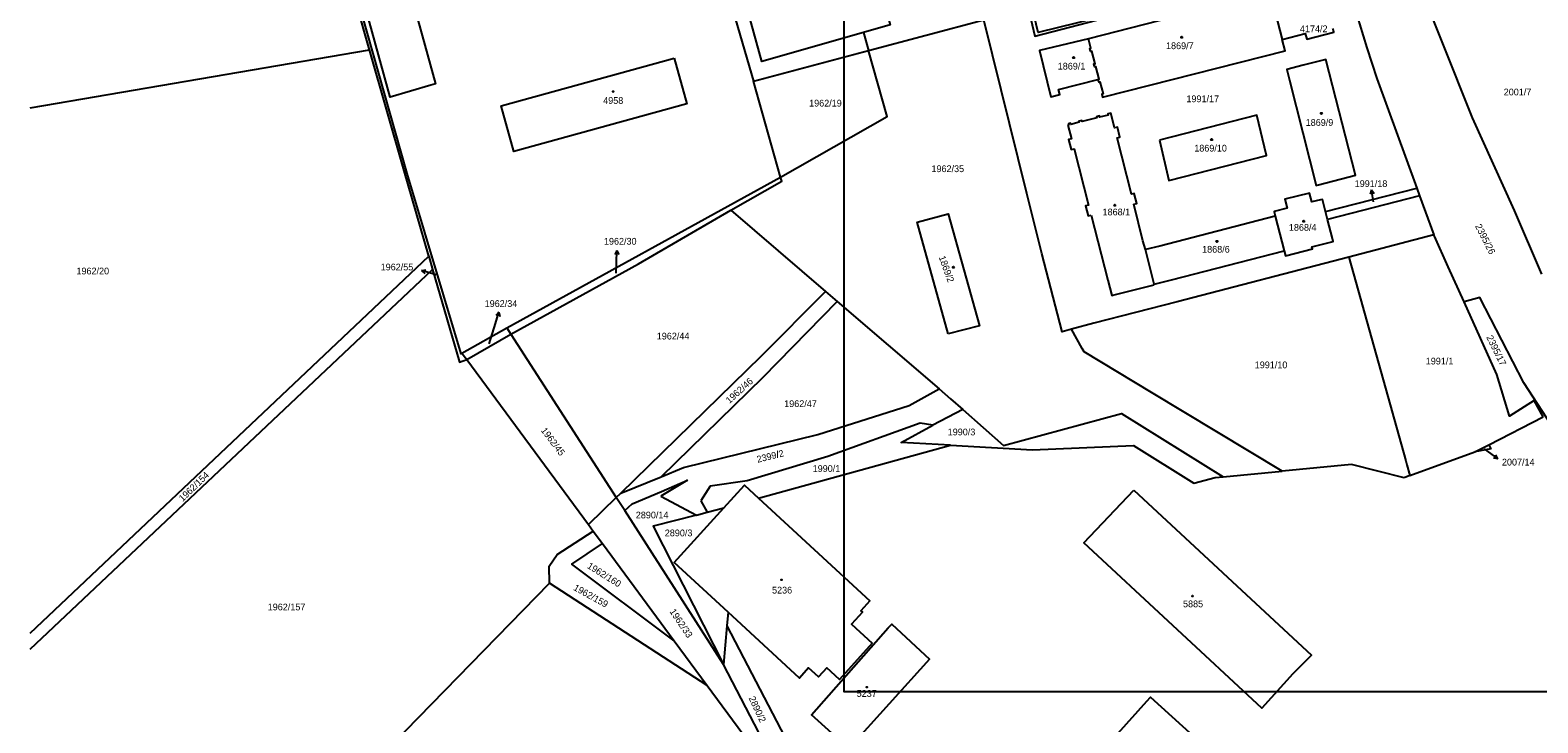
# Model space of a CAD drawing. Extents: x -667048 to -665920, y -1108425 to -1107247.
# Drawn here: x -667043.5 to -666663.6, y -1108191.2 to -1108016.8 of the extents above; entities that cross this region are included whole.
import ezdxf

# ---------------------------------------------------------------- set-up
doc = ezdxf.new("R2010")
doc.units = 0
for name, color, linetype in [('Default', 7, 'Continuous'), ('Hranice parcel', 7, 'Continuous'), ('Parcelní čísla', 7, 'Continuous'), ('Pop_ PČ_ popisy', 7, 'Continuous'), ('Vrstva 2', 7, 'Continuous'), ('Značky budov', 7, 'Continuous')]:
    doc.layers.add(name, color=color, linetype=linetype)

# ---------------------------------------------------------------- blocks, each defined once
blk = doc.blocks.new('4.021')
at = {"layer": 'Default'}
blk.add_circle((-7, 1), 175, dxfattribs=at)
blk = doc.blocks.new('10291')
at = {"layer": 'Default'}
for p, q in [((0, 3001), (-500, 2001)), ((0, 1), (0, 3001)), ((0, 3001), (500, 2001))]:
    blk.add_line(p, q, dxfattribs=at)

msp = doc.modelspace()

# ---------------------------------------------------------------- linework, layer by layer
at = {"layer": 'Hranice parcel'}
for points in [[(-666891.29, -1107926.58), (-666861.25, -1108029.69)], [(-666979.93, -1107942.01), (-666948.55, -1108052.87)], [(-666833.56, -1108017.4), (-666859.17, -1108024.68), (-666875.35, -1107965.92), (-666865.66, -1107962.99), (-666851.87, -1108012.02), (-666837.29, -1108007.83), (-666838.85, -1108002.7), (-666837.63, -1108002.35)], [(-666957.96, -1108021.81), (-666971.4, -1107974.51)], [(-666955.64, -1107978.55), (-666941.34, -1108030.34), (-666942.51, -1108030.68), (-666952.78, -1108033.65), (-666967.07, -1107981.86), (-666957.09, -1107978.97), (-666955.64, -1107978.55)], [(-666837.63, -1108002.35), (-666827.26, -1107999.36), (-666824.99, -1108006.76), (-666828.9, -1108007.97), (-666826.78, -1108015.47), (-666833.56, -1108017.4)], [(-666803.23, -1108014.21), (-666792.01, -1108011.23), (-666790.36, -1108018.29), (-666770.32, -1108013.15), (-666760.82, -1108010.71), (-666743.74, -1108006.33), (-666717.9, -1107999.7)], [(-666695.01, -1108001.76), (-666680.18, -1108038.91)], [(-666790.99, -1108011.46), (-666776.28, -1108007.84), (-666774.82, -1108013.77), (-666789.53, -1108017.38), (-666790.99, -1108011.46)], [(-666731.16, -1108007.34), (-666741.77, -1108010.04), (-666776.85, -1108018.98)], [(-666730.43, -1108010.12), (-666728.05, -1108019.21)], [(-666832.27, -1108021.94), (-666803.23, -1108014.21)], [(-666792.38, -1108057.96), (-666803.23, -1108014.21)], [(-666709.08, -1108013.58), (-666708.59, -1108015.23), (-666706.74, -1108021.23), (-666704.24, -1108029.02), (-666694.11, -1108056.64)], [(-666833.56, -1108017.4), (-666832.27, -1108021.94)], [(-666776.85, -1108018.98), (-666789.16, -1108021.98), (-666786.3, -1108033.59), (-666784.09, -1108033.03), (-666784.43, -1108031.72), (-666774.46, -1108029.2)], [(-666774.46, -1108029.2), (-666774.17, -1108029.12), (-666775, -1108025.98), (-666775.29, -1108026.06), (-666775.48, -1108025.33), (-666775.19, -1108025.26), (-666776.02, -1108022.12), (-666776.31, -1108022.2), (-666776.5, -1108021.47), (-666776.22, -1108021.39), (-666776.85, -1108018.98)], [(-666774.46, -1108029.2), (-666774.37, -1108029.56), (-666774.27, -1108029.92), (-666773.98, -1108029.85), (-666773.18, -1108032.89), (-666773.47, -1108032.97), (-666773.28, -1108033.69), (-666772.99, -1108033.61), (-666727.32, -1108021.99), (-666728.05, -1108019.21)], [(-666728.05, -1108019.21), (-666722.24, -1108017.68), (-666721.84, -1108019.07), (-666715.02, -1108017.34), (-666715.23, -1108016.53), (-666715.26, -1108016.42)], [(-667043.46, -1108036.37), (-666957.96, -1108021.81)], [(-666949.22, -1108052.27), (-666957.96, -1108021.81)], [(-666861.25, -1108029.69), (-666832.27, -1108021.94)], [(-666854.42, -1108053.87), (-666827.55, -1108038.58), (-666832.27, -1108021.94)], [(-666881.2, -1108023.83), (-666878.02, -1108035.4), (-666921.62, -1108047.4), (-666924.79, -1108035.83), (-666881.2, -1108023.83)], [(-666722.73, -1108025.66), (-666726.86, -1108026.72), (-666726.18, -1108029.4), (-666719.45, -1108055.9), (-666719.35, -1108055.88), (-666718.87, -1108055.75), (-666709.61, -1108053.31), (-666717.05, -1108024.2), (-666722.73, -1108025.66)], [(-666854.42, -1108053.87), (-666861.25, -1108029.69)], [(-666771.17, -1108037.99), (-666771.24, -1108037.69), (-666771.98, -1108037.88), (-666771.91, -1108038.18), (-666774.03, -1108038.71), (-666774.1, -1108038.41), (-666774.84, -1108038.6), (-666774.77, -1108038.9), (-666778.44, -1108039.83), (-666778.52, -1108039.53), (-666779.27, -1108039.72), (-666779.19, -1108040.02), (-666781.29, -1108040.55), (-666781.37, -1108040.25), (-666781.86, -1108040.38), (-666781.79, -1108040.67), (-666782.01, -1108040.73)], [(-666765.41, -1108060.66), (-666764.68, -1108060.48), (-666765.32, -1108057.97), (-666766.04, -1108058.15), (-666769.65, -1108043.97), (-666768.92, -1108043.79), (-666769.56, -1108041.27), (-666770.29, -1108041.45), (-666771.17, -1108037.99)], [(-666758.98, -1108044.5), (-666756.6, -1108054.63), (-666731.98, -1108048.38), (-666734.45, -1108038.18), (-666758.98, -1108044.5)], [(-666782.01, -1108040.73), (-666781.12, -1108044.19), (-666781.85, -1108044.37), (-666781.2, -1108046.89), (-666780.47, -1108046.7), (-666776.83, -1108060.84), (-666777.56, -1108061.03), (-666776.91, -1108063.55), (-666776.19, -1108063.36)], [(-666680.18, -1108038.91), (-666669.62, -1108062.22)], [(-666949.22, -1108052.27), (-666948.55, -1108052.87)], [(-666943.03, -1108073.7), (-666949.22, -1108052.27)], [(-666948.55, -1108052.87), (-666934.94, -1108098.28), (-666934.67, -1108098.13)], [(-666923.4, -1108091.78), (-666854.42, -1108053.87)], [(-666866.92, -1108062.13), (-666854.13, -1108054.85), (-666854.42, -1108053.87)], [(-666717.13, -1108062.49), (-666694.11, -1108056.64)], [(-666694.11, -1108056.64), (-666693.42, -1108058.53)], [(-666781.15, -1108092.07), (-666783.45, -1108092.77), (-666788.61, -1108073.09), (-666792.38, -1108057.96)], [(-666762.51, -1108072.05), (-666763.12, -1108069.85), (-666765.41, -1108060.66)], [(-666717.13, -1108062.49), (-666717.91, -1108059.42), (-666718.4, -1108059.54), (-666720.56, -1108060.08), (-666721.13, -1108057.82), (-666727.39, -1108059.41), (-666726.83, -1108061.64), (-666730.09, -1108062.46), (-666729.79, -1108063.67)], [(-666693.42, -1108058.53), (-666716.62, -1108064.47)], [(-666693.42, -1108058.53), (-666689.81, -1108068.36)], [(-666922.37, -1108093.38), (-666890.21, -1108075.64), (-666866.92, -1108062.13)], [(-666866.92, -1108062.13), (-666843.08, -1108082.6)], [(-666812.18, -1108093.28), (-666820.02, -1108065.2), (-666812.23, -1108063.05), (-666804.31, -1108091.26), (-666812.18, -1108093.28)], [(-666776.19, -1108063.36), (-666771.96, -1108079.76), (-666770.97, -1108083.64), (-666770.72, -1108083.58), (-666760.29, -1108080.91)], [(-666729.79, -1108063.67), (-666758.89, -1108071.24), (-666762.51, -1108072.05)], [(-666729.79, -1108063.67), (-666727.54, -1108072.39)], [(-666727.54, -1108072.39), (-666727.23, -1108073.6), (-666720.41, -1108071.86), (-666720.54, -1108071.38), (-666715.2, -1108070.01), (-666715.39, -1108069.29), (-666716.62, -1108064.47)], [(-666716.62, -1108064.47), (-666717.13, -1108062.49)], [(-666669.62, -1108062.22), (-666662.76, -1108078.25)], [(-666689.81, -1108068.36), (-666711.24, -1108074.01)], [(-666682.24, -1108085.26), (-666686.2, -1108076.44), (-666689.69, -1108068.69), (-666689.81, -1108068.36)], [(-666760.33, -1108080.77), (-666762.51, -1108072.05)], [(-666760.33, -1108080.77), (-666755.93, -1108079.65), (-666727.54, -1108072.39)], [(-667043.46, -1108168.6), (-666943.03, -1108073.7)], [(-666943.03, -1108073.7), (-666942.06, -1108077.05)], [(-666711.24, -1108074.01), (-666754.53, -1108085.19), (-666775.5, -1108090.61), (-666781.15, -1108092.07)], [(-666711.24, -1108074.01), (-666696.93, -1108125.25), (-666696.64, -1108126.27), (-666695.89, -1108128.98)], [(-667043.46, -1108172.66), (-666942.06, -1108077.05)], [(-666942.06, -1108077.05), (-666935.31, -1108100.4), (-666933.46, -1108099.77)], [(-666894.66, -1108133.41), (-666859.27, -1108098.86), (-666843.08, -1108082.6)], [(-666843.08, -1108082.6), (-666840.12, -1108085.14)], [(-666760.29, -1108080.91), (-666760.33, -1108080.77)], [(-666640.58, -1108144.39), (-666645.54, -1108138.8), (-666649.92, -1108132.08), (-666667.17, -1108105.62), (-666678.27, -1108084.15), (-666682.24, -1108085.26)], [(-666884.51, -1108129.25), (-666858.83, -1108104.18), (-666840.12, -1108085.14)], [(-666840.12, -1108085.14), (-666814.5, -1108107.14)], [(-666664.53, -1108110.05), (-666667.09, -1108111.66), (-666670.81, -1108114.02), (-666674.01, -1108103.55), (-666682.24, -1108085.26)], [(-666934.67, -1108098.13), (-666923.4, -1108091.78)], [(-666933.46, -1108099.77), (-666922.37, -1108093.38)], [(-666923.4, -1108091.78), (-666922.37, -1108093.38)], [(-666922.37, -1108093.38), (-666895.79, -1108134.5)], [(-666728.05, -1108127.89), (-666761.01, -1108108.03), (-666777.97, -1108097.82), (-666778.44, -1108096.96), (-666781.15, -1108092.07)], [(-666934.67, -1108098.13), (-666933.46, -1108099.77)], [(-666933.46, -1108099.77), (-666902.8, -1108141.32)], [(-666822.01, -1108111.33), (-666814.5, -1108107.14)], [(-666814.5, -1108107.14), (-666811.6, -1108109.63), (-666808.52, -1108112.35)], [(-666662.32, -1108114.15), (-666664.53, -1108110.05)], [(-666878.87, -1108126.94), (-666845.06, -1108118.66), (-666822.01, -1108111.33)], [(-666808.52, -1108112.35), (-666816.07, -1108116.27)], [(-666808.52, -1108112.35), (-666798.23, -1108121.41), (-666768.57, -1108113.31), (-666742.88, -1108129.31)], [(-666676.01, -1108121.19), (-666662.32, -1108114.15)], [(-666819.27, -1108115.75), (-666842.47, -1108124.13)], [(-666811.62, -1108121.31), (-666824.07, -1108120.63), (-666816.07, -1108116.27)], [(-666816.07, -1108116.27), (-666819.27, -1108115.75)], [(-666859.95, -1108134.62), (-666811.62, -1108121.31)], [(-666811.62, -1108121.31), (-666790.92, -1108122.44), (-666765.51, -1108121.36), (-666750.32, -1108130.9), (-666744.94, -1108129.45), (-666742.88, -1108129.31)], [(-666679.53, -1108123.01), (-666676.01, -1108121.19)], [(-666676.01, -1108121.19), (-666675.46, -1108122.23), (-666679.53, -1108123.01)], [(-666842.47, -1108124.13), (-666862.82, -1108130.31), (-666872.11, -1108131.64)], [(-666695.89, -1108128.98), (-666679.53, -1108123.01)], [(-666894.66, -1108133.41), (-666884.51, -1108129.25)], [(-666884.51, -1108129.25), (-666878.87, -1108126.94)], [(-666742.88, -1108129.31), (-666728.05, -1108127.89)], [(-666697.29, -1108129.49), (-666710.55, -1108126.21), (-666728.05, -1108127.89)], [(-666695.89, -1108128.98), (-666697.29, -1108129.49)], [(-666895.79, -1108134.5), (-666894.66, -1108133.41)], [(-666893.68, -1108137.77), (-666891.8, -1108136.11), (-666884.42, -1108132.95), (-666877.84, -1108130.13)], [(-666877.84, -1108130.13), (-666884.61, -1108134.17)], [(-666872.11, -1108131.64), (-666874.52, -1108135.31)], [(-666868.73, -1108137.1), (-666863.48, -1108131.36), (-666859.95, -1108134.62)], [(-666725.37, -1108178.9), (-666733.15, -1108187.55), (-666778.02, -1108145.88), (-666765.41, -1108132.63)], [(-666765.41, -1108132.63), (-666720.7, -1108174.15), (-666725.37, -1108178.9)], [(-666895.79, -1108134.5), (-666902.8, -1108141.32)], [(-666893.68, -1108137.77), (-666895.79, -1108134.5)], [(-666884.61, -1108134.17), (-666875.63, -1108138.9)], [(-666867.64, -1108163.37), (-666881.26, -1108150.81), (-666868.73, -1108137.1)], [(-666874.52, -1108135.31), (-666872.87, -1108138.18)], [(-666872.87, -1108138.18), (-666868.73, -1108137.1)], [(-666859.95, -1108134.62), (-666831.91, -1108160.48), (-666834.2, -1108162.99), (-666833.81, -1108163.35), (-666836.55, -1108166.35), (-666831.31, -1108171.19), (-666839.61, -1108180.28), (-666842.76, -1108177.37), (-666844.85, -1108179.66), (-666847.34, -1108177.37), (-666849.68, -1108179.93), (-666867.64, -1108163.37)], [(-666868.77, -1108176.51), (-666893.68, -1108137.77)], [(-666875.63, -1108138.9), (-666886.48, -1108141.71), (-666868.77, -1108176.51)], [(-666875.63, -1108138.9), (-666872.87, -1108138.18)], [(-666912.59, -1108156.07), (-666912.69, -1108151.73), (-666910.68, -1108148.87), (-666901.6, -1108142.94)], [(-666902.8, -1108141.32), (-666901.6, -1108142.94)], [(-666901.6, -1108142.94), (-666899.3, -1108146.06)], [(-666881.2, -1108170.58), (-666906.97, -1108151.3), (-666899.3, -1108146.06)], [(-666899.3, -1108146.06), (-666881.2, -1108170.58)], [(-666994.96, -1108240.52), (-666912.59, -1108156.07)], [(-666872.92, -1108181.8), (-666912.59, -1108156.07)], [(-666867.64, -1108163.37), (-666867.93, -1108166.76)], [(-666867.93, -1108166.76), (-666868.77, -1108176.51)], [(-666867.93, -1108166.76), (-666838.73, -1108222.85)], [(-666827.35, -1108167.31), (-666826.35, -1108166.37), (-666816.89, -1108175.22), (-666837.22, -1108197.66), (-666846.59, -1108189.16), (-666827.35, -1108167.31)], [(-666881.2, -1108170.58), (-666872.92, -1108181.8)], [(-666849.72, -1108213.24), (-666868.77, -1108176.51)], [(-666872.92, -1108181.8), (-666849.72, -1108213.24)], [(-666757.86, -1108204.83), (-666757.48, -1108204.69), (-666769.47, -1108193.89), (-666762.11, -1108185.76), (-666761.22, -1108184.78), (-666743.33, -1108200.94), (-666741.27, -1108198.79), (-666739.6, -1108200.28), (-666741.61, -1108202.57), (-666739.03, -1108204.94)]]:
    msp.add_lwpolyline(points, dxfattribs=at)
at = {"layer": 'Pop_ PČ_ popisy'}
for points in [[(-666895.81, -1108078.01), (-666895.73, -1108075.29)], [(-666941.18, -1108078.45), (-666942, -1108078.2)], [(-666927.81, -1108095.82), (-666926.24, -1108090.68)], [(-666677.2, -1108122.22), (-666676.13, -1108122.99)]]:
    msp.add_lwpolyline(points, dxfattribs=at)
at = {"layer": 'Vrstva 2'}
msp.add_lwpolyline([(-666838.39, -1107343.37), (-666244.39, -1107343.37), (-666244.39, -1108183.37), (-666838.39, -1108183.37)], close=True, dxfattribs=at)

# ---------------------------------------------------------------- block references
at = {"layer": 'Pop_ PČ_ popisy'}
for p, xscale, yscale, rotation in [((-666705.06, -1108060.02), 0.0010000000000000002, 0.0010000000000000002, 8.999999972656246), ((-666895.73, -1108075.29), 0.001, 0.0010000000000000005, -2.000000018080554), ((-666942, -1108078.2), 0.0010000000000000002, 0.0010000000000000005, 72.99999999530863), ((-666926.24, -1108090.68), 0.0010000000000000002, 0.0010000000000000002, -17.00000000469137), ((-666676.13, -1108122.99), 0.001, 0.0010000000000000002, -126.00000004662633)]:
    msp.add_blockref('10291', p, dxfattribs=dict(at, xscale=xscale, yscale=yscale, rotation=rotation))
at = {"layer": 'Značky budov'}
for p, xscale, yscale in [((-666753.34, -1108018.59), 0.0010000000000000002, 0.0010000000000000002), ((-666780.57, -1108023.72), 0.0010000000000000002, 0.0010000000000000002), ((-666896.55, -1108032.29), 0.0006700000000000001, 0.0006700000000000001), ((-666718.16, -1108037.78), 0.0010000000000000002, 0.0010000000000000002), ((-666745.81, -1108044.36), 0.0010000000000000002, 0.0010000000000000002), ((-666770.2, -1108060.91), 0.0010000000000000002, 0.0010000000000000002), ((-666722.62, -1108064.92), 0.0010000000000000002, 0.0010000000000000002), ((-666744.49, -1108070.01), 0.0010000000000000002, 0.0010000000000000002), ((-666810.87, -1108076.5), 0.0010000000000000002, 0.0010000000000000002), ((-666854.2, -1108155.21), 0.0006700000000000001, 0.0006700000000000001), ((-666750.6, -1108159.3), 0.0006700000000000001, 0.0006700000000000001), ((-666832.7, -1108182.23), 0.0006700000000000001, 0.0006700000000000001)]:
    msp.add_blockref('4.021', p, dxfattribs=dict(at, xscale=xscale, yscale=yscale))

# ---------------------------------------------------------------- texts
at = {"layer": 'Parcelní čísla'}
for s, p in [('4174/2', (-666723.58, -1108017.33)), ('1869/7', (-666757.31, -1108021.6)), ('1869/1', (-666784.59, -1108026.74)), ('4958', (-666899.1, -1108035.38)), ('1962/19', (-666847.22, -1108036.05)), ('1991/17', (-666752.17, -1108034.96)), ('2001/7', (-666672.24, -1108033.24)), ('1869/9', (-666722.13, -1108040.91)), ('1869/10', (-666750.2, -1108047.38)), ('1962/35', (-666816.4, -1108052.56)), ('1991/18', (-666709.78, -1108056.31)), ('1868/1', (-666773.3, -1108063.45)), ('1868/4', (-666726.36, -1108067.33)), ('1962/30', (-666898.91, -1108070.82)), ('1868/6', (-666748.22, -1108072.84)), ('1962/20', (-667031.79, -1108078.31)), ('1962/55', (-666955.16, -1108077.31)), ('1962/34', (-666928.96, -1108086.51)), ('1962/44', (-666885.6, -1108094.7)), ('1991/1', (-666691.88, -1108100.99)), ('1991/10', (-666734.96, -1108101.94)), ('1962/47', (-666853.5, -1108111.71)), ('1990/3', (-666812.31, -1108118.83)), ('2007/14', (-666672.69, -1108126.43)), ('1990/1', (-666846.33, -1108128.04)), ('2890/14', (-666890.88, -1108139.74)), ('2890/3', (-666883.58, -1108144.25)), ('5236', (-666856.56, -1108158.66)), ('1962/157', (-666983.61, -1108162.9)), ('5885', (-666753.03, -1108162.12)), ('5237', (-666835.24, -1108184.67))]:
    msp.add_text(s, height=1.7, dxfattribs=at).set_placement(p)
for s, rotation, p in [('2395/26', 297, (-666679.5, -1108066.15)), ('1869/2', 290, (-666814.6, -1108073.97)), ('2395/17', 296, (-666676.65, -1108094.14)), ('1962/46', 42, (-666867.29, -1108110.95)), ('1962/45', 307, (-666914.88, -1108117.62)), ('2399/2', 14, (-666860.19, -1108125.76)), ('1962/154', 44, (-667005.02, -1108135.63)), ('1962/160', 328, (-666903.3, -1108152.14)), ('1962/159', 331, (-666906.76, -1108157.68)), ('1962/33', 304, (-666882.45, -1108163.2)), ('2890/2', 295, (-666862.49, -1108185))]:
    msp.add_text(s, height=1.7, rotation=rotation, dxfattribs=at).set_placement(p)

doc.saveas('drawing.dxf')
